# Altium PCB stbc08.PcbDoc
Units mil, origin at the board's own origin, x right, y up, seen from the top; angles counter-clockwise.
Board outline 6000 x 4000 mil, 2 copper layers (Top Layer, Bottom Layer); 13 components, 9 nets, 50 pads, 6 vias.
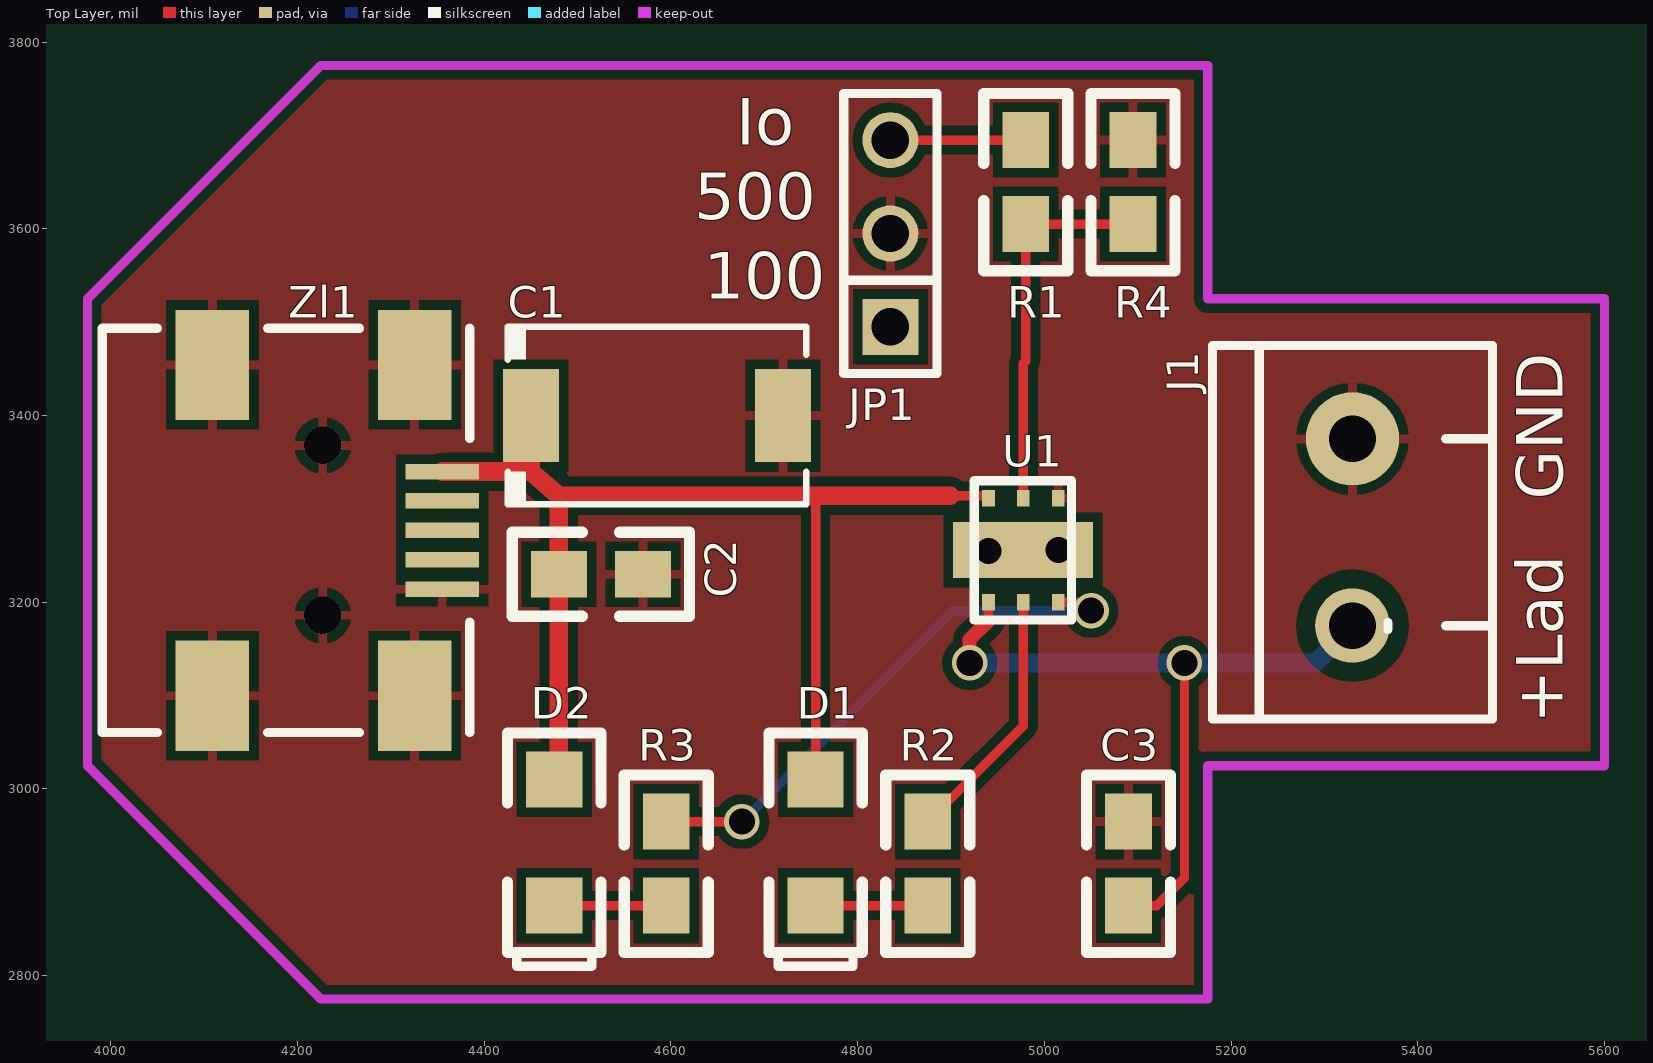
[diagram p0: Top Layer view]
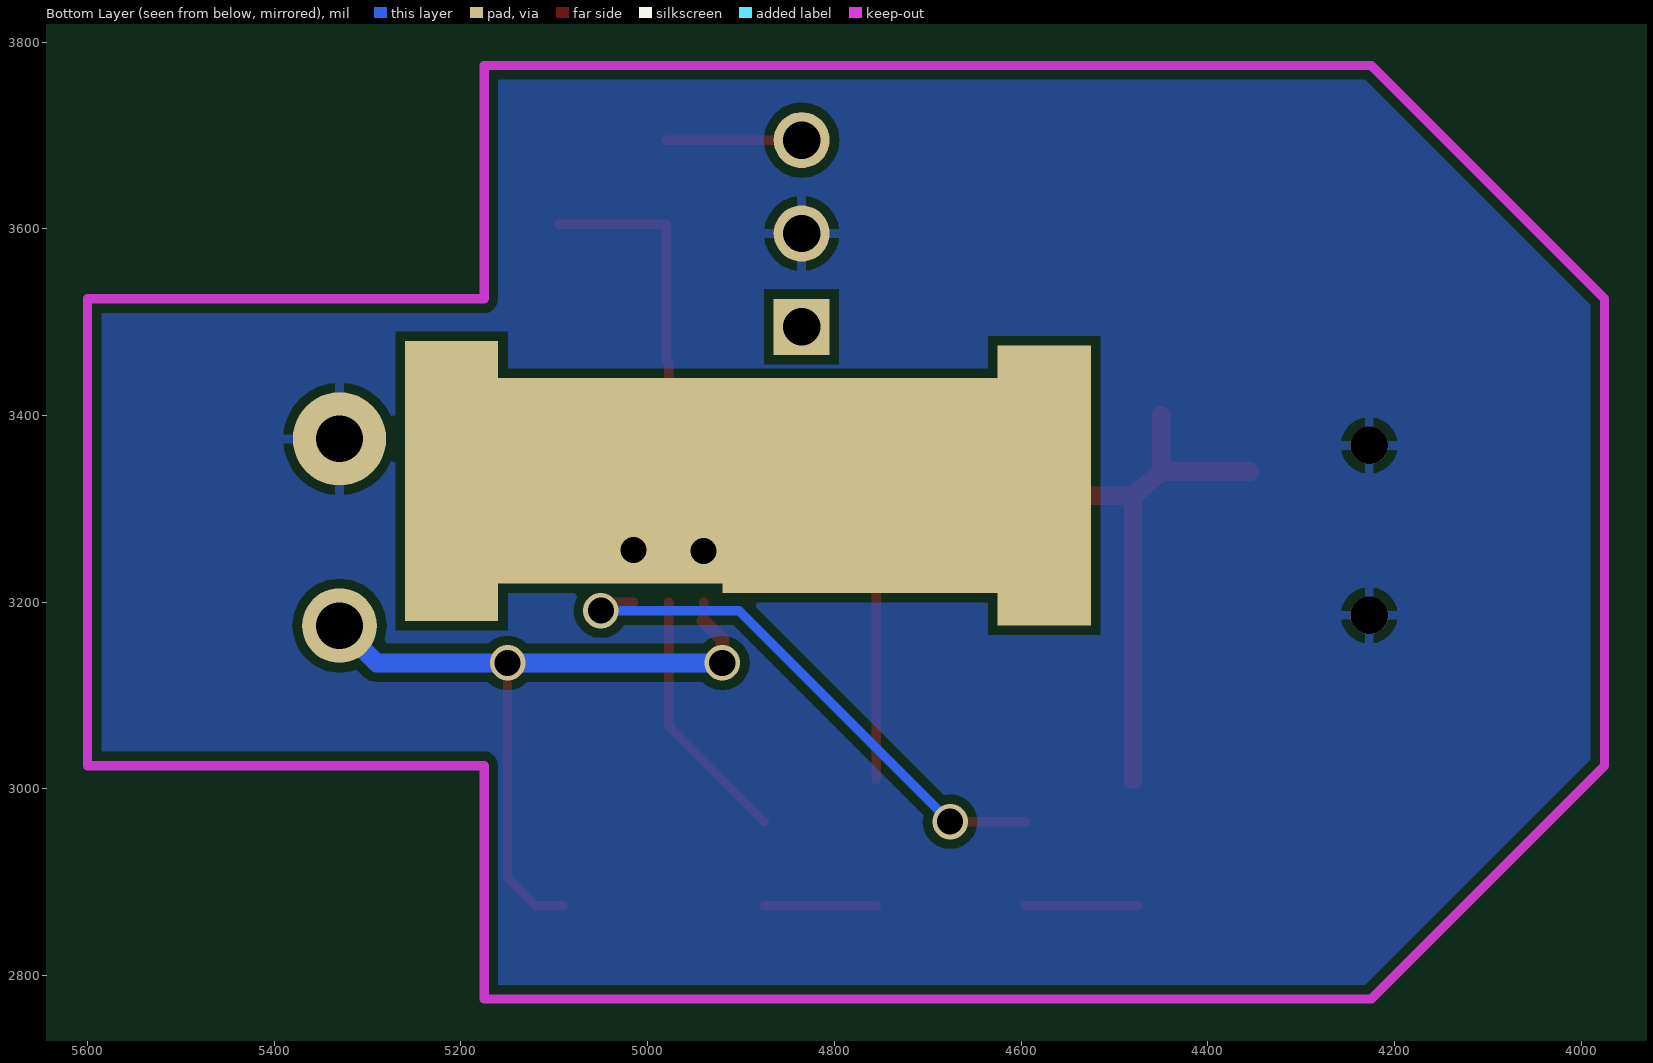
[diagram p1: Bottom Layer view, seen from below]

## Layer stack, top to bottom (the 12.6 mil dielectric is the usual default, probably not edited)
Top Layer: signal copper 1.4
Dielectric: dielectric 12.6, FR-4, Dk 4.8
Bottom Layer: signal copper 1.4

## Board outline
1000,1000 7000,1000 7000,5000 1000,5000

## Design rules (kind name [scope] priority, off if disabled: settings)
Clearance [All] p1: gap=10
PolygonConnect [All] p1: connectstyle=Relief reliefconductorwidth=10 reliefentries=4 polygonreliefangle="90 Angle"
RoutingVias [All] p1: holewidth=28 width=50 viastyle="Through Hole" minholewidth=28 minwidth=50 maxholewidth=28 maxwidth=50
SilkscreenOverComponentPads [All] p1: minsilkscreentomaskgap=10
SolderMaskExpansion [All] p1: expansion=4
Width [All] p1: maxlimit=10 minlimit=10 preferedwidth=10
27 further rules are at their usual default settings.

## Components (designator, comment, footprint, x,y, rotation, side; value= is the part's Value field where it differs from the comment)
C1 "47uF" CE_SMD_SIZE_D 4445,3400 r0 top
C2 "1uF" 0805 4570,3230 r180 top
C3 "1uF" 0805 5090,2875 r90 top
D1 "LED" 1206_LED 4755,3010 r270 top
D2 "LED" 1206_LED 4475,3010 r270 top
J1 "CON2" ARK2 5330,3175 r0 top
JP1 "JP" sip-3 4835,3495 r90 top
R1 "2,2k" 0805 4980,3695 r270 top
R2 "1k" 0805 4875,2965 r270 top
R3 "1k" 0805 4595,2965 r270 top
R4 "10k" 0805 5095,3695 r270 top
U1 "STBC08" DFN6_3x3 4940,3200 r90 top
Zl1 "MINIUSB_B" MiniUSB_B 4355,3340 r180 top

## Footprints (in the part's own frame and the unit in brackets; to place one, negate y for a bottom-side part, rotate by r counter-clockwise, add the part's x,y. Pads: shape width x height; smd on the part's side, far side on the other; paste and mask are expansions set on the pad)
0805 [mil]
  rect 60x50 smd: 1(0,0) 2(90,0)
  silkscreen extent -50,-45 140,45
1206_LED [mil]
  rect 60x60 smd: 1(0,0) 2(135,0)
  silkscreen extent -50,-50 200,50
ARK2 [mil]
  round 80 hole 50: 1(0,0)
  round 100 hole 50: 2(0,200)
  silkscreen extent -150,-100 150,300
CE_SMD_SIZE_D [mil]
  rect 60x100 smd: 1(5,0) 2(275,0)
  silkscreen extent -20,-95 300,95
DFN6_3x3 [mm] "Robiony dla STB08"
  rect 1.524x3.81 smd: 0(1.422,-0.94)
  rect 1.524x3.81 smd far side: 0(1.422,-0.94)
  rect 0.45x0.35 smd: 1(0,0) 2(0,-0.95) 3(0,-1.9) 4(2.829,-1.9) 5(2.829,-0.95) 6(2.829,0)
  silkscreen extent -0.48,-2.26 3.3,0.38
MiniUSB_B [mm]
  rect 2x3 smd: 0(0.75,6.1) 0(0.75,-2.9) 0(6.25,6.1) 0(6.25,-2.9)
  round 1.016 hole 1.016: 0(3.25,3.911) 0(3.25,-0.711)
  rect 2x0.42 smd: 1(0,0) 2(0,0.8) 3(0,1.6) 4(0,2.4) 5(0,3.2)
  silkscreen extent -0.75,-3.9 9.25,7.1
sip-3 [mil]
  rect 60x60 hole 40: 1(0,0)
  round 60 hole 40: 2(100,0) 3(200,0)
  silkscreen extent -50,-50 250,50

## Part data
C1: library part CP, "Capacitor"
C2 C3: library part Cap, "Capacitor"
J1: "Connector"
JP1: "Jumper"
R1 R2 R3 R4: library part RES2
U1: library part STBC08PMQ

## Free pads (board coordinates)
  rect 100x300 smd far side: 0(4575,3325) 0(5210,3330)
  rect 300x100 smd far side: 0(4770,3260) 0(4770,3355) 0(4770,3390) 0(5065,3270) 0(5065,3355) 0(5065,3390)

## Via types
v1: diameter 38, hole 28, Top Layer to Bottom Layer, tented both sides, 6 vias

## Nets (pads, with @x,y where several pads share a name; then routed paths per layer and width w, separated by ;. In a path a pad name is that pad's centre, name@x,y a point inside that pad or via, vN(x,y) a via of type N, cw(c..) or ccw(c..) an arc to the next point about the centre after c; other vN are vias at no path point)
GND: C1.2 C2.1 C3.2 J1.2 JP1.2 R4.1 U1.4 Zl1.0 Zl1.5
NetC1_1: C1.1 C2.2 D1.1 D2.1 U1.6 Zl1.1 | length 1263.8
  Top Layer w10: D1.1 4755,3314 ; 4899,3314 4937.36,3314 U1.6
  Top Layer w20: Zl1.1 4450,3340 ; C1.1 4450,3340 ; D2.1@4480,3010 C2.2 4480,3314 ; 4899,3314 4755,3314 4480,3314 ; 4450,3340 4480,3314
NetC3_1: C3.1 J1.1 U1.1 | length 802.3
  Top Layer w10: 4940,3180 U1.1 ; C3.1 5120,2875 5150,2905 v1(5150,3135)
  Top Layer w15: v1(4920,3135) 4920,3160 4940,3180
  Bottom Layer w20: v1(4920,3135) 5290,3135 J1.1
NetD1_2: D1.2 R2.2 | length 120
  Top Layer w10: D1.2 R2.2
NetD2_2: D2.2 R3.2 | length 120
  Top Layer w10: D2.2 R3.2
NetJP1_3: JP1.3 R1.1 | length 145
  Top Layer w10: JP1.3 R1.1
NetR1_2: R1.2 R4.2 U1.5 | length 409.7
  Top Layer w10: U1.5 4977.4,3456 4980,3458.6 R1.2 R4.2
NetR2_1: R2.1 U1.2 | length 277.4
  Top Layer w10: R2.1 4977.4,3067.4 U1.2
NetR3_1: R3.1 U1.3 | length 587.5
  Top Layer w10: R3.1 v1(4676,2965) ; U1.3 5041,3200 v1(5050,3191)
  Bottom Layer w10: v1(4676,2965) 4902,3191 v1(5050,3191)
pads on no net: JP1.1 U1.0 Zl1.2 Zl1.3 Zl1.4
copper on no net:
  other v1: 4940,3255 5015,3256

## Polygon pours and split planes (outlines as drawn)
GND on Top Layer "Top Layer-No Net" (solid, remove dead copper, pour order 2): 3960,3020 4225,2755 4230,2755 5200,2755 5195,2760 5195,3015 5610,3015 5615,3020 5615,3540 5190,3540 5190,3785 4225,3785 4220,3790 3955,3525 3955,3520 3955,3025 3960,3020
GND on Bottom Layer "Top Layer-No Net" (solid, remove dead copper, pour order 4): 3960,3025 4225,2760 4225,2755 5190,2755 5190,3010 5605,3010 5610,3015 5610,3540 5195,3540 5190,3545 5190,3790 4225,3790 4210,3775 3960,3525 3960,3520 3960,3015

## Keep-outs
Keep-Out Layer:
  lines w10: 3975,3025 4225,2775 5175,2775 5175,3025 5600,3025 5600,3525 5175,3525 5175,3775 4225,3775 3975,3525 3975,3275 3975,3025

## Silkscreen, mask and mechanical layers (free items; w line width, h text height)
Top Overlay:
  text "Io" at 4670,3690 h50
  text "500" at 4625,3610 h50
  text "100" at 4635,3525 h50
  text "GND" at 5555,3310 h50 r90
  text "+Lad" at 5555,3070 h50 r90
